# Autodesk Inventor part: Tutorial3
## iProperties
Shininess: 64.0
Length Units: 11269
Angle Units: 11279
Time Units: 11290
Mass Units: 11283
Length Display Precision: 3
Angle Display Precision: 2
Compacted: True
Part Number: Tutorial3
Document SubType Name: Modeling
Created: 2002-12
Designer: deepak
Density: 1 g/cm^3
Density: 0.0
Volumn: 0.0
Area: 0.0
PropertySet Name: Model Information
Control State: 0
Master: False
Checked Out: False
Author: deepak
